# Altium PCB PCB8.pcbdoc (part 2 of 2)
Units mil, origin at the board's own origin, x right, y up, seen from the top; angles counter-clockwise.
Board outline 4659.3 x 3372.91 mil, 4 copper layers (Top Layer, Inner1, Inner2, Bottom Layer); 143 components, 120 nets, 588 pads, 154 vias.
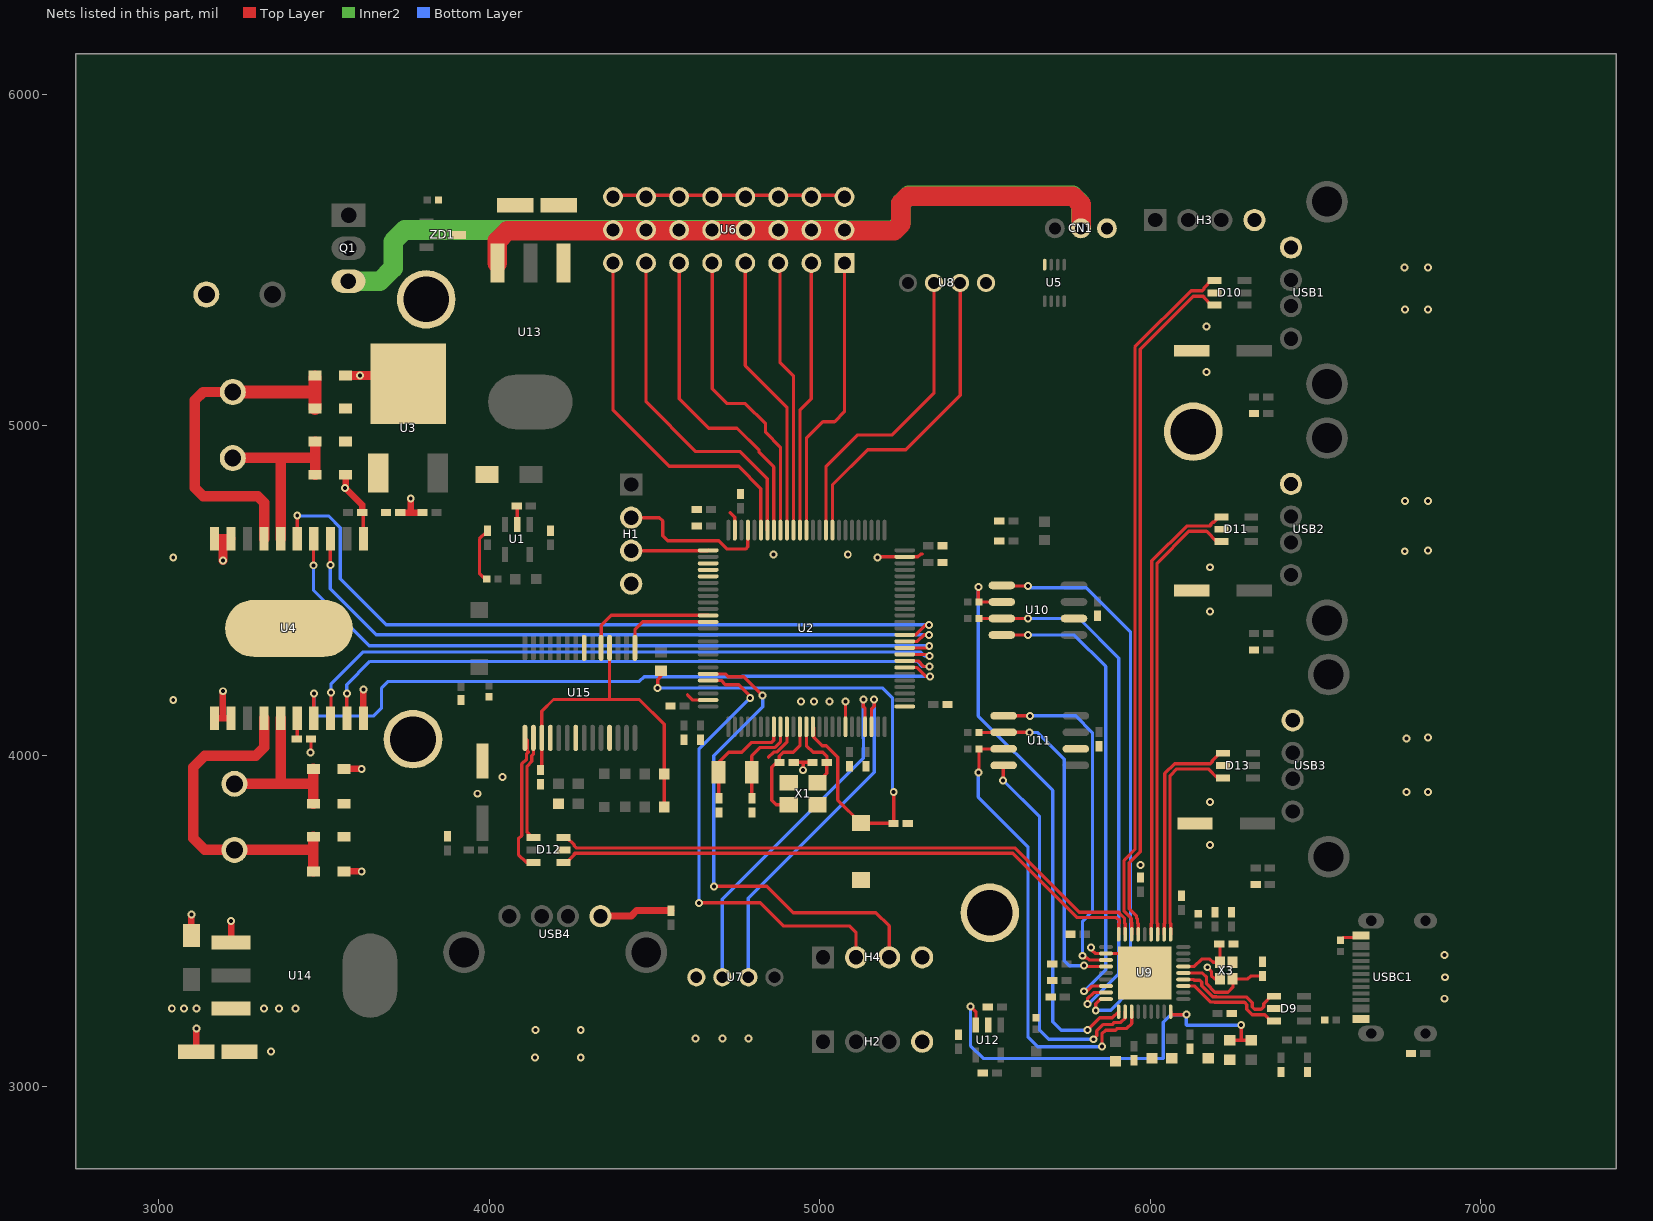
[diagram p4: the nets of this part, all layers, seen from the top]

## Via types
v1: diameter 24.02, hole 12.01, Top Layer to Bottom Layer, 154 vias

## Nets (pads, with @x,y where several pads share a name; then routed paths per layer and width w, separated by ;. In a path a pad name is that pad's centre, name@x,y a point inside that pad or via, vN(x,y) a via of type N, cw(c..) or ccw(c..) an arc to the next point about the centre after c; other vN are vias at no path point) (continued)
ENA: U2.34 U4.8 | length 2035.8
  Top Layer w10: U4.8@3520,4113.15 3522.24,4115.39 v1(3522.24,4191.06) ; U2.34@5257.24,4306.06 5327.44,4306.06 v1(5331.8,4301.7)
  Bottom Layer w10: v1(3522.24,4191.06) 3522.24,4217.04 3618.91,4313.71 5304.8,4313.71 5316.8,4301.7 v1(5331.8,4301.7)
ENB: U2.35 U4.14 | length 2165
  Top Layer w10: v1(3469.16,4575.74) 3469.16,4655.61 U4.14@3470,4656.45 ; U2.35@5257.24,4325.74 5325.43,4325.74 v1(5331.39,4331.7)
  Bottom Layer w10: v1(3469.16,4575.74) 3469.16,4500.65 3637.08,4332.73 5330.37,4332.73 v1(5331.39,4331.7)
ENC1_1: U2.22 U7.3 | length 1100.6
  Top Layer w10: v1(5132.17,4169.53) 5132.17,4147.63 5137.17,4142.63 U2.22@5137.17,4087.56
  Bottom Layer w10: U7.3@4705.63,3329.81 4705.63,3565.43 5132.17,3991.97 5132.17,4022.85 5132.4,4023.08 5132.4,4052.13 5132.17,4052.36 v1(5132.17,4169.53)
ENC1_2: U2.23 U7.2 | length 1083.3
  Top Layer w10: U2.23@5156.85,4087.56 5156.85,4141.65 5165,4149.8 v1(5165,4169.8)
  Bottom Layer w10: U7.2@4784.37,3329.81 4784.37,3569.17 5165,3949.8 v1(5165,4169.8)
ENC3_1: U2.59 U8.3 | length 975.4
  Top Layer w10: U2.59@5038.74,4682.04 5038.74,4818.54 5145,4924.8 5260,4924.8 5425,5089.8 5425,5429.17 U8.3@5424.37,5429.8
ENC3_2: U2.60 U8.2 | length 944.5
  Top Layer w10: U2.60@5019.06,4682.04 5019.06,4873.86 5115,4969.8 5220,4969.8 5345.63,5095.43 U8.2@5345.63,5429.8
GND: C1.2 C2.1 C3.1 C4.1 C5.1 C6.1 C7.1 C8.1 C9.1 C10.1 C11.1 C12.1 C13.1 C14.2 C15.2 C16.2 C17.2 C18.2 C19.1 C20.1 C21.2 C22.2 C23.1 C24.2 C25.2 C26.2 C27.1 C28.2 C29.2 C30.1 C31.1 C32.2 C33.1 C34.2 C35.1 C36.2 C37.1 C38.2 C39.2 C40.2 C41.2 C42.1 C43.1 C44.2 C45.2 C46.2 C47.2 C48.1 C50.1 C51.2 C52.2 C53.2 C54.2 C55.2 C56.2 C57.2 C58.2 C59.2 C60.1 C61.2 C62.1 CN1.3 D5.2 D6.2 D7.2 D8.2 D9.2 D10.2 D11.2 D12.2 D13.2 H1.4 H2.4 H3.4 H4.4 P3.1 pad.1 pad.2 R1.1 R3.2 R4.1 R5.2 R6.1 R7.1 R8.1 R9.1 R10.1 R15.1 R19.2 R20.1 R21.1 RST.1 U1.2 U2.10 U2.19 U2.26 U2.49 U2.74 U2.99 U3.2 U4.1 U4.2 U4.10 U4.11 U4.19 U4.20 U4.21 U5.4 U6.17 U6.18 U6.19 U6.20 U6.21 U6.22 U6.23 U6.24 U7.4 U8.4 U9.11 U9.37 U10.6 U11.6 U12.2 U13.1 U14.1 U15.7 U15.18 U15.21 U15.25 USB1.4 USB2.4 USB3.4 USB4.4 USBC1.A1 USBC1.A12 USBC1.B1 USBC1.B12 X1.2 X1.4 X3.2 X3.4 | length 3246.3
  Top Layer w10: v1(3460,4009.8) 3461.46,4011.26 C11.1@3461.46,4049.8 ; C12.1@3616.46,4734.8 3620,4731.26 U4.11@3620,4656.45 ; R1.1@3988.72,4534.01 3970.93,4551.8 3970.93,4655.3 3990.93,4675.3 4000.93,4675.3 C3.1@3995.76,4680.47 ; U1.2@4085.76,4699.43 4085.76,4752.03 C1.2@4088.54,4754.8 ; U6.24@4390,5694.8 4490,5694.8 4590,5694.8 4690,5694.8 4790,5694.8 4890,5694.8 4990,5694.8 U6.17@5090,5694.8 ; 4600,4184.8 4616.54,4168.26 U2.99@4662.76,4168.26 ; 4730,4734.8 4743.46,4721.34 U2.74@4743.46,4682.04 ; 4845,3994.8 4860.98,4010.79 4870.81,4010.79 4900.94,4040.92 U2.10@4900.94,4087.56 ; C2.1@4921.46,3979.8 4949.99,3979.8 ; v1(4950,3955.9) 4950,3979.8 ; C5.1@4978.54,3979.8 4949.99,3979.8 ; U2.19@5078.11,4087.56 v1(5078.11,4164.18) ; v1(5175,4599.8) 5176.54,4601.34 U2.49@5257.24,4601.34 5296.54,4601.34 5305,4609.8 5310,4609.8 ; v1@5825,3409.8 5833.1,3401.7 U9.11@5865.86,3401.7 5923.8,3401.7 U9.37@5982.86,3342.64 ; v1(6172.28,3360) 6185,3347.29 6185,3334.8 6195.12,3324.68 X3.4@6210.79,3324.68 ; R4.1@6575,3441.84 6583.04,3449.88 USBC1.B1@6637.59,3449.88 USBC1.A12@6637.59,3461.69 ; USBC1.A1@6637.59,3197.91 USBC1.B12@6637.59,3209.72
  Top Layer w19.68: C47.2@3100,3451.19 v1(3100,3519.8) ; C46.2@3114.62,3104.8 3115,3105.18 v1(3115,3174.8) ; U4.1@3170,4113.15 3194.15,4113.15 ; v1(3195,4194.8) 3195,4114.01 3194.15,4113.15 ; U14.1@3219.86,3434.8 3220,3434.94 v1(3220,3499.8) ; U4.2@3220,4113.15 3194.15,4113.15 ; D5.2@3561.16,3649.8 v1(3615,3649.8) ; D6.2@3561.16,3959.8 v1(3615,3959.8) ; D8.2@3566.16,4849.8 3566.16,4810.97 v1(3565,4809.8) 3616.46,4758.34 C12.1@3616.46,4734.8 ; U4.10@3620,4113.15 v1(3620,4199.8) ; C9.1@3731.46,4734.8 3763,4734.8 ; v1(3763.24,4777.64) 3763,4777.39 3763,4734.8 ; C10.1@3798.54,4734.8 3763,4734.8
  Top Layer w21.65: USB4.4@4337,3514.35 4337.45,3514.8 4430,3514.8 4446.46,3531.26 C50.1@4550,3531.26
  Top Layer w27.56: U4.20@3170,4656.45 3195.43,4656.45 ; v1(3195,4589.8) 3195,4656.03 3195.43,4656.45 ; U4.19@3220,4656.45 3195.43,4656.45 ; D7.2@3566.16,5149.8 v1(3610,5149.8) 3729.8,5149.8 U3.2@3755,5124.61
  other v1: 4139.47,3087.17 4277.4,3086.9 4625,3144.8 4705.57,3144.8 4785,3144.8 4140,3169.8 4277.4,3170.63 6890,3264.8 6890.92,3329.8 6890,3396.63 5820.01,3419.5 5970,3669.8 6180,3729.8 6180,3859.8 3965,3884.8 6775,3889.8 6840,3889.8 4041.16,3934.8 6775,4051.75 6840,4054.8 4943.69,4164.18 4983.26,4164.18 5030.28,4164.18 6180,4436.19 6180,4569.8 4860.6,4609.01 5085,4609.01 6769.56,4618.16 6840,4619.8 6770,4769.8 6840,4769.8 6170,5159.8 6170,5298.49 6770,5349.8 6839.72,5349.78 6768.78,5477 6839.72,5477
IN1: U2.32 U4.7 | length 2174.6
  Top Layer w10: U4.7@3470,4113.15 v1(3470,4188.15) ; U2.32@5257.24,4266.69 5293.11,4266.69 5320.38,4239.43 v1(5334.04,4239.43)
  Bottom Layer w10: v1(3470,4188.15) 3470,4129.86 3480,4119.86 3649.95,4119.86 3674.95,4144.86 3674.95,4204.86 3694.57,4224.48 4454.67,4224.48 4468.9,4238.7 4763.9,4238.7 4765,4239.8 5333.66,4239.8 v1(5334.04,4239.43)
IN2: U2.33 U4.9 | length 1981.5
  Top Layer w10: U4.9@3570.06,4113.15 v1(3570.06,4188.15) ; U2.33@5257.24,4286.37 5298.43,4286.37 5315.43,4269.38 v1(5332.35,4269.38)
  Bottom Layer w10: v1(3570.06,4188.15) 3570,4214.8 3640,4284.8 5295,4284.8 5310.43,4269.38 v1(5332.35,4269.38)
IN3: U2.36 U4.13 | length 2101.5
  Top Layer w10: v1(3520,4576.45) U4.13@3520,4656.45 ; U2.36@5257.24,4345.43 5295.63,4345.43 5315.68,4365.49 v1(5330.54,4365.49)
  Bottom Layer w10: v1(3520,4576.45) 3520,4504.8 3659.32,4365.49 v1(5330.54,4365.49)
IN4: U2.37 U4.15 | length 2295.2
  Top Layer w10: U4.15@3420,4656.45 v1(3420,4726.45) ; U2.37@5257.24,4365.12 5290.32,4365.12 5320.68,4395.48 v1(5330.98,4395.48)
  Bottom Layer w10: v1(3420,4726.45) 3421.65,4724.8 3515,4724.8 3550,4689.8 3550,4534.8 3689.32,4395.48 v1(5330.98,4395.48)
MISO: U2.79
MOSI: U2.80
NRST: C8.2 C49.2 RST.2 U2.14 | length 1619
  Top Layer w10: v1(4510,4204.8) 4510,4229.8 4520,4239.8 C49.2@4520,4257.24 ; U2.14@4979.69,4087.56 4982.48,4084.77 4982.48,4054.98 5007.65,4029.8 5020,4029.8 5055,3994.8 5055,3865.82 RST.2@5125,3795.82 5222.52,3795.82 C8.2@5223.54,3794.8 5223.98,3795.24 v1(5223.98,3889.61)
  Bottom Layer w10: v1(4510,4204.8) 5190,4204.8 5220,4174.8 5220,3893.59 v1(5223.98,3889.61)
OSC32_IN: C6.2 U2.8 X2.2 | length 344.9
  Top Layer w10: C6.2@4695,3871.26 4695,3948.48 X2.2@4693.79,3949.69 4693.79,3978.59 4725,4009.8 4765,4009.8 4795,4039.8 4855,4039.8 4861.57,4046.37 U2.8@4861.57,4087.56
OSC32_OUT: C7.2 U2.9 X2.1 | length 279.1
  Top Layer w10: C7.2@4795,3871.26 4795,3948.88 X2.1@4794.19,3949.69 4794.19,3998.99 4820,4024.8 4865,4024.8 4881.26,4041.06 U2.9@4881.26,4087.56
OSC_IN: C2.2 U2.12 X1.1 | length 338.5
  Top Layer w10: X1.1@4906.69,3851.34 4868.47,3851.34 4855,3864.8 4855,3964.8 4870,3979.8 C2.2@4878.54,3979.8 4877.93,3980.42 4877.93,3997.73 4890,4009.8 4920,4009.8 4940.32,4030.12 U2.12@4940.32,4087.56
OSC_OUT: C5.2 U2.13 X1.3 | length 224.5
  Top Layer w10: U2.13@4960,4087.56 4960,4029.8 4980,4009.8 5010,4009.8 5022.07,3997.73 5022.07,3980.42 C5.2@5021.46,3979.8 5021.46,3946.42 X1.3@4993.31,3918.27
OUT1: D1.2 D5.1 P1.1 U4.4 | length 1026.6
  Top Layer w31.5: U4.4@3320,4113.15 3320,4024.8 3295,3999.8 3140,3999.8 3105,3964.8 3105,3749.8 3140,3714.8 P1.1@3230,3714.8 3468.63,3714.8 3468.84,3715.01 ; D5.1@3468.84,3649.8 3468.84,3715.01 ; D1.2@3468.84,3754.8 3468.84,3715.01
OUT2: D2.2 D6.1 P1.2 U4.5 | length 542.4
  Top Layer w31.5: P1.2@3230,3914.8 3369.3,3914.8 ; U4.5@3370,4113.15 3370,3915.5 3369.3,3914.8 ; 3468.8,3914.8 3369.3,3914.8 ; D2.2@3468.84,3854.8 3468.84,3914.83 D6.1@3468.84,3959.8
OUT3: D4.2 D8.1 P2.1 U4.16 | length 594
  Top Layer w31.5: P2.1@3225,4899.8 3226.14,4900.94 3370.6,4900.94 ; U4.16@3370,4656.45 3370,4900.34 3370.6,4900.94 ; D8.1@3473.84,4849.8 3473.84,4900.94 ; D4.2@3473.84,4949.8 3473.84,4900.94 ; 3370.6,4900.94 3473.84,4900.94
OUT4: D3.2 D7.1 P2.2 U4.17 | length 1071.5
  Top Layer w31.5: P2.2@3225,5099.8 3135,5099.8 3110,5074.8 3110,4809.8 3135,4784.8 3300,4784.8 3320,4764.8 U4.17@3320,4656.45
  Top Layer w39.37: P2.2@3225,5099.8 3473.14,5099.8 3473.84,5100.5 ; D3.2@3473.84,5049.8 3473.84,5100.5 ; D7.1@3473.84,5144.8 3473.84,5100.5
PA8: U2.67 U6.5 | length 925.4
  Top Layer w10: U6.5@4675,5489.8 4675,5109.8 4720,5064.8 4775,5064.8 4836.26,5003.54 4836.26,4978.37 4881.26,4933.37 U2.67@4881.26,4682.04
PA9: U2.68 U6.6 | length 976.3
  Top Layer w10: U6.6@4575,5489.8 4575,5079.8 4665,4989.8 4750,4989.8 4816.57,4923.23 4816.57,4918.06 4861.57,4873.06 U2.68@4861.57,4682.04
PA10: U2.69 U6.7 | length 1038.8
  Top Layer w10: U6.7@4475,5489.8 4475,5069.8 4625,4919.8 4760,4919.8 4841.89,4837.91 U2.69@4841.89,4682.04
PA11: U2.70 U6.8 | length 1116
  Top Layer w10: U6.8@4375,5489.8 4375,5044.8 4545,4874.8 4755,4874.8 4822.2,4807.6 U2.70@4822.2,4682.04
PC6: U2.63 U6.1 | length 875.9
  Top Layer w10: U2.63@4960,4682.04 4960,4959.8 5010,5009.8 5045,5009.8 5075,5039.8 U6.1@5075,5489.8
PC7: U2.64 U6.2 | length 822.1
  Top Layer w10: U2.64@4940.32,4682.04 4940.32,5045.12 4975,5079.8 U6.2@4975,5489.8
PC8: U2.65 U6.3 | length 829.6
  Top Layer w10: U6.3@4875,5489.8 4880,5489.8 4880,5189.8 4920.63,5149.17 U2.65@4920.63,4682.04
PC9: U2.66 U6.4 | length 859.9
  Top Layer w10: U6.4@4775,5489.8 4775,5179.8 4900.94,5053.86 U2.66@4900.94,4682.04
RX1: U2.86 U15.5 | length 404.8
  Top Layer w10: U15.5@4338.98,4325.83 4338.98,4393.78 4370,4424.8 4662.13,4424.8 U2.86@4662.76,4424.17
SCK: U2.78
SCL: H4.3 U2.95 | length 1504.7
  Top Layer w10: U2.95@4662.76,4247 4714.93,4247 4723.24,4238.7 4770.71,4238.7 v1(4827.6,4181.81) ; v1(4680,3604.8) 4840,3604.8 4920,3524.8 5170,3524.8 5210,3484.8 H4.3@5210,3389.8
  Bottom Layer w10: v1(4680,3604.8) 4680,3999.8 4827.6,4147.4 v1(4827.6,4181.81)
SDA: H4.2 U2.96 | length 1423.4
  Top Layer w10: v1(4635,3554.8) 4820,3554.8 4890,3484.8 5090,3484.8 5110,3464.8 H4.2@5110,3389.8 ; U2.96@4662.76,4227.32 4702.48,4227.32 4715,4214.8 4755,4214.8 4790,4179.8 v1(4790,4174.8)
  Bottom Layer w10: v1(4635,3554.8) 4635,4019.8 v1(4790,4174.8)
SWCLK: H1.3 U2.76 | length 233.3
  Top Layer w10: H1.3@4430,4619.8 4661.54,4619.8 U2.76@4662.76,4621.02
SWDIO: H1.2 U2.72 | length 471.6
  Top Layer w10: H1.2@4430,4719.8 4515,4719.8 4525,4709.8 4525,4664.8 4540,4649.8 4695,4649.8 4720,4624.8 4775.76,4624.8 4782.83,4631.88 U2.72@4782.83,4682.04
TX1: U2.87 U15.1 | length 286.7
  Top Layer w10: U15.1@4441.34,4325.83 4441.34,4381.14 4465,4404.8 4662.45,4404.8 U2.87@4662.76,4404.49
USB1_DM: D12.4 U15.16 | length 319.8
  Top Layer w10: U15.16@4134.25,4053.77 4134.25,4004.1 4129.45,3999.3 4129.45,3982.68 4115,3968.22 4115,3768.46 4131.26,3752.2 D12.4@4134.76,3752.2
USB1_DP: D12.6 U15.15 | length 424.5
  Top Layer w10: U15.15@4108.66,4053.77 4116.1,4046.33 4116.1,4013.75 4118.25,4011.6 4118.25,4010.73 4113.45,4005.93 4113.45,3989.3 4099,3974.85 4099,3758.21 4089,3748.21 4089,3700.8 4112.4,3677.4 D12.6@4134.76,3677.4
USB_HUB_NOCS1: R12.1 U9.13 U11.2 | length 1034.7
  Top Layer w10: R12.1@5482.04,4069.8 5555.85,4069.8 U11.2@5556.48,4070.43 5634.37,4070.43 v1(5635,4069.8) ; v1(5800,3364.8) 5802.47,3362.33 U9.13@5865.86,3362.33
  Bottom Layer w10: v1(5635,4069.8) 5660,4069.8 5740,3989.8 5740,3379.8 5755,3364.8 v1(5800,3364.8)
USB_HUB_NOCS2: R13.2 U9.17 U10.3 | length 1639.8
  Top Layer w10: R13.2@5482.04,4414.8 U10.3@5550.85,4414.8 v1(5630,4414.8) ; v1(5810,3248.91) 5810,3264.8 5828.79,3283.59 U9.17@5865.86,3283.59
  Bottom Layer w10: v1(5630,4414.8) 5785,4414.8 5905,4294.8 5905,3339.8 5814.11,3248.91 v1(5810,3248.91)
USB_HUB_NOCS3: R11.1 U9.19 U10.2 | length 1758.1
  Top Layer w10: v1(5480,4509.8) 5480,4466.84 R11.1@5482.04,4464.8 U10.2@5550.85,4464.8 U10.2@5552.72,4462.93 ; v1(5810,3169.8) 5847.22,3207.02 5885.49,3207.02 U9.19@5904.12,3225.64
  Bottom Layer w10: v1(5480,4509.8) 5480,4119.8 5705,3894.8 5705,3194.8 5730,3169.8 v1(5810,3169.8)
USB_HUB_NOCS4: R14.2 U9.21 U11.3 | length 1421
  Top Layer w10: v1(5480,3949.17) 5482.04,3951.21 R14.2@5482.04,4019.8 5555.85,4019.8 U11.3@5556.48,4020.43 ; v1(5853.85,3120.96) 5853.85,3158.65 5865,3169.8 5895,3169.8 5900,3174.8 5928.57,3174.8 5943.49,3189.72 U9.21@5943.49,3225.64
  Bottom Layer w10: v1(5480,3949.17) 5480,3874.8 5630,3724.8 5630,3149.8 5660,3119.8 5817.48,3119.8 5818.07,3119.22 5852.11,3119.22 v1(5853.85,3120.96)
USB_HUB_PWR1: U9.12 U11.1 | length 1053.1
  Top Layer w10: U11.1@5556.48,4120.43 v1(5635.58,4120.43) ; v1(5795,3394.8) 5802.01,3387.8 5809.52,3387.8 5815.31,3382.01 U9.12@5865.86,3382.01
  Bottom Layer w10: v1(5635.58,4120.43) 5774.37,4120.43 5825,4069.8 5825,3529.8 5795,3499.8 v1(5795,3394.8)
USB_HUB_PWR2: U9.16 U10.4 | length 1435.2
  Top Layer w10: U10.4@5550.85,4364.8 v1(5630,4364.8) ; v1(5800,3287.45) 5807.64,3287.45 5823.37,3303.17 5865.76,3303.17 U9.16@5865.86,3303.27
  Bottom Layer w10: v1(5630,4364.8) 5770,4364.8 5865,4269.8 5865,3352.45 v1(5800,3287.45)
USB_HUB_PWR3: U9.18 U10.1 | length 1718.7
  Top Layer w10: U10.1@5550.85,4514.8 5552.72,4512.93 v1(5630,4512.93) ; v1(5835,3229.8) 5835,3249.8 5849.1,3263.9 U9.18@5865.86,3263.9
  Bottom Layer w10: v1(5630,4512.93) 5635,4507.93 5806.87,4507.93 5940,4374.8 5940,3289.8 5880,3229.8 v1(5835,3229.8)
USB_HUB_PWR4: U9.20 U11.4 | length 1172.1
  Top Layer w10: v1(5555,3924.8) 5555,3968.95 U11.4@5556.48,3970.43 ; v1(5827.59,3142.21) 5837.59,3152.21 5837.59,3167.39 5856.84,3186.64 5884.8,3186.64 5891.16,3193.01 5910.95,3193.01 5923.8,3205.85 U9.20@5923.8,3225.64
  Bottom Layer w10: v1(5555,3924.8) 5665,3814.8 5665,3169.8 5692.59,3142.21 v1(5827.59,3142.21)
USBDM_DN1: D13.3 U9.1 | length 660.4
  Top Layer w10: U9.1@6061.6,3459.64 6061.6,3491.3 6059.75,3493.14 6059.75,3939.55 6080,3959.8 6175,3959.8 6202.4,3932.4 D13.3@6219.76,3932.4
USBDM_DN2: D11.3 U9.3 | length 1370.7
  Top Layer w10: U9.3@6022.23,3459.64 6022.23,3491.3 6020.38,3493.14 6020.38,4582.56 6116.31,4678.49 6170,4678.49 6201.09,4647.4 D11.3@6214.76,4647.4
USBDM_DN3: D10.3 U9.6 | length 2099.3
  Top Layer w10: U9.6@5963.17,3459.64 5963.17,3491.3 5961.33,3493.14 5961.33,3505.3 5958.39,3508.24 5958.39,3514.37 5936.48,3536.28 5936.48,3676.28 5969.69,3709.49 5969.69,5229.49 6130,5389.8 6160.73,5389.8 6162.67,5387.86 6162.67,5384.78 6185.05,5362.4 D10.3@6194.76,5362.4
USBDM_DN4: D12.3 U9.8 | length 1849.8
  Top Layer w10: D12.3@4225.24,3752.2 4234.95,3752.2 4257.33,3729.83 4257.33,3726.74 4263.27,3720.8 5590.4,3720.8 5785,3526.21 5905.51,3526.21 5906.46,3525.26 5906.46,3523.85 5921.96,3508.35 5921.96,3493.14 5923.8,3491.3 U9.8@5923.8,3459.64
USBDM_UP: D9.3 U9.30 | length 326.7
  Top Layer w10: U9.30@6099.86,3303.27 6134.08,3303.27 6182.57,3254.79 6193.68,3254.79 6194.67,3253.8 6285,3253.8 6292.07,3246.73 6292.07,3233.18 6308.51,3216.73 6345.72,3216.73 6365.05,3197.4 D9.3@6374.76,3197.4
USBDP_DN1: D13.1 U9.2 | length 690.4
  Top Layer w10: U9.2@6041.91,3459.64 6041.91,3491.3 6043.75,3493.14 6043.75,3946.18 6073.37,3975.8 6181.73,3975.8 6187.67,3981.74 6187.67,3984.83 6210.05,4007.2 D13.1@6219.76,4007.2
USBDP_DN2: D11.1 U9.4 | length 1397.6
  Top Layer w10: U9.4@6002.54,3459.64 6002.54,3491.3 6004.38,3493.14 6004.38,4589.18 6109.69,4694.49 6180.42,4694.49 6182.67,4696.74 6182.67,4699.83 6189.11,4706.26 6192.19,4706.26 6208.13,4722.2 D11.1@6214.76,4722.2
USBDP_DN3: D10.1 U9.7 | length 2125.9
  Top Layer w10: U9.7@5943.49,3459.64 5943.49,3494.98 5942.39,3496.08 5942.39,3507.74 5920.48,3529.65 5920.48,3682.91 5953.69,3716.12 5953.69,5236.12 6123.37,5405.8 6156.73,5405.8 6162.67,5411.74 6162.67,5414.83 6185.05,5437.2 D10.1@6194.76,5437.2
USBDP_DN4: D12.1 U9.9 | length 1820.8
  Top Layer w10: D12.1@4225.24,3677.4 4234.95,3677.4 4257.33,3699.78 4257.33,3702.86 4259.27,3704.8 5583.78,3704.8 5778.37,3510.21 5897.47,3510.21 5905.96,3501.73 5905.96,3493.14 5904.12,3491.3 U9.9@5904.12,3459.64
USBDP_UP: D9.1 U9.31 | length 348.6
  Top Layer w10: U9.31@6099.86,3322.96 6131.51,3322.96 6133.35,3321.12 6149.98,3321.12 6155.98,3315.12 6155.98,3304 6189.19,3270.79 6200.31,3270.79 6201.3,3269.8 6291.63,3269.8 6308.07,3253.36 6308.07,3239.8 6315.14,3232.73 6335,3232.73 6342.67,3240.41 6342.67,3249.83 6365.05,3272.2 D9.1@6374.76,3272.2
VBUS_DET: R2.1 R6.2 U9.27 U12.3 | length 1333.4
  Top Layer w10: v1(5456.45,3241.75) 5472.6,3225.6 U12.3@5472.6,3185.22 ; U9.27@6061.6,3225.64 6061.6,3218.21 6063.14,3216.66 v1(6108.84,3216.66) ; R6.2@6240,3139.46 6275.27,3139.46 ; v1(6275,3184.8) 6275,3139.73 6275.27,3139.46 ; R2.1@6305,3139.46 6275.27,3139.46
  Bottom Layer w10: v1(5456.45,3241.75) 5456.45,3121.75 5494.13,3084.07 6038.76,3084.07 6038.76,3193.57 6061.86,3216.66 v1(6108.84,3216.66) 6108.84,3185.96 6110,3184.8 v1(6275,3184.8)
VCC: C9.2 C11.2 C44.1 C46.1 CN1.2 D1.1 D2.1 D3.1 D4.1 Q1.3 U3.1 U4.6 U6.9 U6.10 U6.11 U6.12 U6.13 U6.14 U6.15 U6.16 U13.3 U14.3 ZD1.3 | length 4558.4
  Top Layer w10: C11.2@3418.54,4049.8 3420,4051.26 U4.6@3420,4113.15
  Top Layer w59.06: U13.3@4025,5489.94 4025,5556.63 4055.91,5587.55 5225.91,5587.55 5245.91,5607.55 5245.91,5670.72 5267.74,5692.55 5765.91,5692.55 5790.91,5667.55 5790.91,5600.72 CN1.2@5790,5599.8
  Inner2 w59.06: Q1.3@3574.8,5434.81 3669.99,5434.8 3710,5474.8 3710,5554.8 3745,5589.8 U6.16@4375,5589.8 U6.15@4475,5589.8 U6.14@4575,5589.8 U6.13@4675,5589.8 U6.12@4775,5589.8 U6.11@4875,5589.8 U6.10@4975,5589.8 U6.9@5075,5589.8 5075.15,5589.66 5224.85,5589.66 5245.15,5609.95 5245.15,5669.66 5270.15,5694.66 5765.15,5694.66 5790,5669.8 CN1.2@5790,5594.8
  other v1: 3340,3104.8 3040.49,3234.8 3077.01,3234.8 3115,3234.8 3320,3234.8 3364.14,3234.8 3415,3234.8 3045,4167.84 3045,4599.8
VCCIO: C48.2 R17.2 R18.2 U15.4 U15.17 | length 1004.3
  Top Layer w10: C48.2@4155,3956.26 4159.84,3961.1 U15.17@4159.84,4053.77 4159.84,4134.64 4195,4169.8 4364.24,4169.8 ; U15.4@4364.57,4325.83 4364.57,4170.13 4364.24,4169.8 ; R18.2@4534.66,3844.8 4529.66,3849.8 R17.2@4529.66,3944.8 4529.66,4095.14 4455,4169.8 4364.24,4169.8
XTALIN: C40.1 U9.33 X3.3 | length 180.1
  Top Layer w10: U9.33@6099.86,3362.33 6132.53,3362.33 6155,3384.8 6180,3384.8 6189.88,3374.92 X3.3@6210.79,3374.92 6210.79,3427.55 C40.1@6208.54,3429.8
XTALOUT: C41.1 U9.32 X3.1 | length 311.6
  Top Layer w10: U9.32@6099.86,3342.64 6157.16,3342.64 6170,3329.8 6170,3309.8 6195,3284.8 6235,3284.8 6250,3299.8 6250,3323.89 X3.1@6249.21,3324.68 6294.88,3324.68 6303.54,3333.34 C41.1@6340,3333.34
pads on no net: U2.1 U2.2 U2.3 U2.4 U2.5 U2.7 U2.15 U2.16 U2.17 U2.18 U2.24 U2.25 U2.30 U2.31 U2.38 U2.39 U2.40 U2.41 U2.42 U2.43 U2.44 U2.45 U2.51 U2.55 U2.56 U2.57 U2.58 U2.61 U2.62 U2.71 U2.77 U2.81 U2.82 U2.83 U2.84 U2.85 U2.88 U2.89 U2.90 U2.91 U2.92 U2.93 U2.97 U2.98 U4.3 U4.18 U15.3 U15.6 U15.8 U15.9 U15.10 U15.11 U15.12 U15.13 U15.14 U15.24 U15.26 U15.27 U15.28 USB4.2 USB4.3 USBC1.A8 USBC1.B8 ZD1.2

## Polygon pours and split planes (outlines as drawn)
3V3_HUB on Inner2 (solid, remove dead copper): 5347.35,3003.9 5329.99,3021.27 5329.99,3127.45 5354.18,3151.64 5635.37,3152.63 5685.33,3189.8 5685.33,3548.32 5732.28,3584.8 6360,3584.8 6400,3544.8 6400,3020.78 6383.12,3003.9
VCC on Top Layer (solid, remove dead copper, pour order 0): 3000,5759.8 3757.87,5759.8 3757.87,3003.9 3000,3003.9
5V_HOST on Inner2 (solid, remove dead copper): 6447.71,3003.9 6435.91,3003.9 6430,3009.8 6430,3404.8 6470,3444.8 6720,3444.8 6760,3404.8 6760,3019.8 6744.09,3003.9
VCC on Top Layer (solid, remove dead copper, pour order 2): 3495,5474.8 3495,5389.8 3690,5389.8 3695,5394.8 3695,5419.8 3700,5424.8 3700,5444.48 3745.46,5489.94 4040.14,5489.94 4055,5504.8 4055,5549.8 4065,5559.8 4125,5559.8 4145,5579.81 4145,5705 4135,5719.8 3979.68,5719.8 3970,5705.4 3970,5634.17 3960,5614.8 3876.43,5614.8 3842.54,5574.8 3723.8,5574.8 3630,5479.8 3500,5479.8
VCC on Inner2 (solid, remove dead copper): 3000,3003.9 3747.94,3003.9 3747.94,3159.8 3660,3247.74 3660,4544.8 3750,4634.8 3750,5759.8 3000,5759.8
GND on Top Layer (solid, remove dead copper, pour order 4): 3818.11,3003.9 3818.11,5759.8 6937.01,5759.8 6937.01,3003.9
+5V on Inner2 (solid, remove dead copper): 3885,5484.8 3885,4716.73 3901.92,4699.8 4250,4699.8 4270,4719.8 4270,4969.8 4315,5014.8 5665,5014.8 5700,5049.8 5700,5124.8 5745,5169.8 5895,5169.8 5900,5174.8 5900,5444.8 5890,5454.8 5700.85,5454.8 5646.85,5508.8 5286,5508.8 5285,5509.8 5220,5444.8 5220,5354.8 5200,5334.8 4283.89,5334.8 4205,5413.7 4205,5469.8 4190,5484.8
+3V3 on Inner2 (solid, remove dead copper): 4075,4629.8 4075,4219.8 4110,4184.8 4465.16,4184.8 4590.16,4059.8 4595,4059.8 4595,4018.58 4608.59,4009.8 5175,4009.8 5230,4039.8 5315,4039.8 5355,4079.8 5355,4852.49 5328.24,4874.8 4365,4874.8 4350,4854.84 4350,4667.5 4336.59,4658.37 4105.21,4658.37 4076.64,4629.8

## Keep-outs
Board Outline Layer:
  lines w10: 3000,3084.8 ccw(c3078.74,3084.8) 3078.74,3006.06 6858.27,3006.06 ccw(c6858.27,3084.8) 6937.01,3084.8 6937.01,5681.06 ccw(c6858.27,5681.06) 6858.27,5759.8 3078.74,5759.8 ccw(c3078.74,5681.06) 3000,5681.06 3000,3084.8

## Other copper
Top Layer:
  drawing of 475 lines, arcs and shapes, not listed
Inner2:
  region net VCC: 5760.47,5630.8 5819.53,5630.8 5819.76,5606.43 5820,5594.8 5760,5594.8 5760.24,5606.43
  region net VCC: 3669.99,5464.33 3669.99,5405.27 3655.22,5405.02 3640.97,5404.35 3627.67,5403.4 3615.75,5402.32 3597.8,5400.29 3590.55,5399.37 3590.55,5470.23 3597.8,5469.31 3615.75,5467.28 3627.67,5466.2 3640.97,5465.25 3655.22,5464.58
  region net +5V: 4900.77,3349.49 4900.77,3310.12 4897.59,3310.33 4894.85,3310.84 4890.25,3311.98 4888.17,3312.22 4886.09,3311.97 4885.01,3311.61 4883.9,3311.05 4882.72,3310.28 4881.48,3309.26 4881.48,3350.35 4882.72,3349.33 4883.9,3348.55 4885.01,3348 4886.09,3347.63 4888.17,3347.39 4890.25,3347.63 4894.85,3348.76 4897.59,3349.28
  region net +5V: 4843.64,3367.62 4883.01,3367.31 4882.79,3364.12 4882.27,3361.39 4881.12,3356.8 4880.87,3354.73 4881.1,3352.65 4881.46,3351.57 4882.01,3350.45 4882.78,3349.27 4883.79,3348.02 4842.71,3348.33 4843.73,3349.56 4844.51,3350.73 4845.08,3351.84 4845.45,3352.92 4845.7,3355 4845.48,3357.09 4844.35,3361.71 4843.85,3364.45
  region net VCC: 5111.15,5619.19 5111.15,5560.13 5093,5559.93 5085.63,5559.82 5074.85,5559.8 5075.15,5619.8 5085.83,5619.67 5093.15,5619.46 5100.46,5619.27
  region net VCC: 5039,5560.28 5039,5619.33 5063.38,5619.57 5075,5619.8 5075,5559.8 5063.38,5560.04
  region net VCC: 4939,5560.28 4939,5619.33 4963.38,5619.57 4975,5619.8 4975,5559.8 4963.38,5560.04
  region net VCC: 5011,5619.33 5011,5560.28 4986.62,5560.04 4975,5559.8 4975,5619.8 4986.62,5619.57
  region net VCC: 4911,5619.33 4911,5560.28 4886.62,5560.04 4875,5559.8 4875,5619.8 4886.62,5619.57
  region net VCC: 4839,5560.28 4839,5619.33 4863.38,5619.57 4875,5619.8 4875,5559.8 4863.38,5560.04
  region net VCC: 4811,5619.33 4811,5560.28 4786.62,5560.04 4775,5559.8 4775,5619.8 4786.62,5619.57
  region net VCC: 4739,5560.28 4739,5619.33 4763.38,5619.57 4775,5619.8 4775,5559.8 4763.38,5560.04
  region net VCC: 4711,5619.33 4711,5560.28 4686.62,5560.04 4675,5559.8 4675,5619.8 4686.62,5619.57
  region net VCC: 4639,5560.28 4639,5619.33 4663.38,5619.57 4675,5619.8 4675,5559.8 4663.38,5560.04
  region net VCC: 4539,5560.28 4539,5619.33 4563.38,5619.57 4575,5619.8 4575,5559.8 4563.38,5560.04
  region net VCC: 4611,5619.33 4611,5560.28 4586.62,5560.04 4575,5559.8 4575,5619.8 4586.62,5619.57
  region net VCC: 4439,5560.28 4439,5619.33 4463.38,5619.57 4475,5619.8 4475,5559.8 4463.38,5560.04
  region net VCC: 4511,5619.33 4511,5560.28 4486.62,5560.04 4475,5559.8 4475,5619.8 4486.62,5619.57
  region net VCC: 4411,5619.33 4411,5560.28 4386.62,5560.04 4375,5559.8 4375,5619.8 4386.62,5619.57
  region net VCC: 4339,5560.28 4339,5619.33 4363.38,5619.57 4375,5619.8 4375,5559.8 4363.38,5560.04
  region net +5V_PI: 4015.67,3492.7 4015.67,3536.01 4019.2,3535.88 4022.46,3535.6 4025.48,3535.31 4028.32,3535.18 4031.05,3535.36 4033.71,3536.01 4035.04,3536.55 4036.38,3537.27 4037.72,3538.18 4039.09,3539.3 4039.09,3489.41 4037.72,3490.53 4036.38,3491.44 4035.04,3492.16 4033.71,3492.7 4031.05,3493.34 4028.32,3493.52 4025.48,3493.4 4022.46,3493.11 4019.2,3492.83
  region net +5V: 6034.69,5527.28 5995.31,5527.28 ccw(c5861.88,5527.28) 5981.54,5586.34 6048.46,5586.34 ccw(c6168.12,5527.28)
  region net +5V: 5029.69,3339.8 4990.31,3339.8 ccw(c4973.5,3339.8) 4976.54,3356.34 5043.46,3356.34 ccw(c5046.5,3339.8)
  region net +5V_USB_PORT3: 5758.19,4579.21 5781.81,4579.21 5782.01,4564.8 5757.99,4564.8
  region net +5V_USB_PORT3: 6366.81,4975.39 6343.19,4975.39 6342.99,4989.8 6367.01,4989.8
  region net 3V3_HUB: 5960.16,3563.82 5979.84,3563.82 5979.94,3561.17 5980.18,3558.67 5980.93,3554.29 5981.67,3551.07 5982.01,3549.41 5957.99,3549.41 5958.33,3551.07 5959.07,3554.29 5959.82,3558.67 5960.06,3561.17
  region net +5V_USB_PORT1: 5776.61,4183.97 5793.32,4167.27 5783.27,4156.94 5766.28,4173.92
  region net +5V_USB_PORT1: 6349.65,3584.21 6373.27,3584.21 6373.47,3569.8 6349.45,3569.8
  region net +5V_USB_PORT4: 5760.37,3913.62 5760.37,3937.24 5774.78,3937.44 5774.78,3913.42
  region net +5V_USB_PORT4: 3934.41,3771.61 3934.41,3747.99 3920,3747.8 3920,3771.81
  region net +5V_USB_PORT2: 5784.41,4326.61 5784.41,4302.99 5770,4302.8 5770,4326.81
  region net +5V_USB_PORT2: 6340.59,4267.99 6340.59,4291.61 6355,4291.81 6355,4267.8
  region net +5V_USB_FIL: 5713.54,4085.18 5699.63,4071.26 5697.69,4073.07 5695.74,4074.66 5692.12,4077.23 5689.32,4078.98 5687.91,4079.92 5704.89,4096.9 5705.82,4095.49 5707.57,4092.68 5710.14,4089.06 5711.74,4087.12
  region net +5V_USB_FIL: 5553.23,3351.95 5567.15,3338.03 5565.34,3336.1 5563.75,3334.15 5561.17,3330.53 5559.43,3327.73 5558.49,3326.31 5541.51,3343.29 5542.92,3344.23 5545.72,3345.98 5549.35,3348.55 5551.29,3350.15
  region net 3V3_HUB: 5459.41,4189.65 5459.41,4169.96 5456.76,4169.87 5454.26,4169.62 5449.88,4168.88 5446.66,4168.13 5445,4167.8 5445,4191.81 5446.66,4191.47 5449.88,4190.73 5454.26,4189.98 5456.76,4189.74
  region net +5V-D1: 3854.84,4765.39 3835.16,4765.39 3835.06,4768.04 3834.82,4770.54 3834.07,4774.93 3833.33,4778.14 3832.99,4779.8 3857.01,4779.8 3856.67,4778.14 3855.93,4774.93 3855.18,4770.54 3854.94,4768.04
  region net +5V-D1: 3549.84,4775.39 3530.16,4775.39 3530.06,4778.04 3529.82,4780.54 3529.07,4784.93 3528.33,4788.14 3527.99,4789.8 3552.01,4789.8 3551.67,4788.14 3550.93,4784.93 3550.18,4780.54 3549.94,4778.04
Bottom Layer:
  region net ENC1_2: 4779.37,3367.47 4789.37,3367.47 4789.46,3365.43 4789.72,3363.65 4790.14,3362.1 4790.71,3360.76 4791.41,3359.58 4792.24,3358.53 4794.23,3356.71 4799.2,3353.22 4802.01,3351.02 4804.91,3348.18 4763.83,3348.18 4766.73,3351.02 4769.54,3353.22 4774.51,3356.71 4776.5,3358.53 4777.33,3359.58 4778.03,3360.76 4778.6,3362.1 4779.02,3363.65 4779.28,3365.43
  region net ENC1_1: 4700.63,3367.47 4710.63,3367.47 4710.72,3365.43 4710.98,3363.65 4711.4,3362.1 4711.97,3360.76 4712.67,3359.58 4713.5,3358.53 4715.49,3356.71 4720.46,3353.22 4723.27,3351.02 4726.17,3348.18 4685.09,3348.18 4687.99,3351.02 4690.8,3353.22 4695.77,3356.71 4697.76,3358.53 4698.59,3359.58 4699.29,3360.76 4699.86,3362.1 4700.28,3363.65 4700.54,3365.43
  region net DEBUG_RX: 5095,3172.07 5105,3186.97 5105.13,3184.66 5105.5,3182.54 5106.09,3180.59 5106.9,3178.8 5107.9,3177.16 5109.09,3175.64 5110.43,3174.23 5111.92,3172.9 5115.27,3170.46 5119.01,3168.18 5127.14,3163.55 5079.53,3148.64 5080.34,3150.2 5081.31,3151.71 5083.58,3154.58 5088.72,3160.04 5091.12,3162.79 5093.13,3165.66 5093.9,3167.16 5094.49,3168.72 5094.87,3170.36
  region net DEBUG_TX: 5205,3180.54 5215,3180.54 5215.11,3177.93 5215.45,3175.7 5215.99,3173.78 5216.71,3172.14 5217.62,3170.72 5218.68,3169.49 5219.89,3168.4 5221.23,3167.4 5224.25,3165.48 5227.62,3163.37 5231.22,3160.71 5233.08,3159.05 5234.94,3157.11 5185.06,3157.11 5186.92,3159.05 5188.78,3160.71 5192.38,3163.37 5195.75,3165.48 5198.77,3167.4 5200.11,3168.4 5201.32,3169.49 5202.38,3170.72 5203.29,3172.14 5204.01,3173.78 5204.55,3175.7 5204.89,3177.93
  region net ENA: 3517.24,4207.47 3527.24,4207.47 3527.33,4206.35 3527.58,4205.22 3528.47,4202.99 3529.74,4200.9 3531.19,4199.07 3513.29,4199.07 3514.74,4200.9 3516.01,4202.99 3516.9,4205.22 3517.15,4206.35
  region net ENB: 3474.16,4559.33 3464.16,4559.33 3464.07,4560.45 3463.82,4561.59 3462.92,4563.82 3461.66,4565.91 3460.21,4567.74 3478.11,4567.74 3476.66,4565.91 3475.39,4563.82 3474.5,4561.59 3474.25,4560.45
  region net VBUS_DET: 6092.43,3211.66 6092.43,3221.66 6093.55,3221.75 6094.68,3222 6096.91,3222.89 6099.01,3224.16 6100.83,3225.61 6100.83,3207.71 6099.01,3209.16 6096.91,3210.43 6094.68,3211.32 6093.55,3211.57
  region net VBUS_DET: 6113.84,3200.25 6103.84,3200.25 6103.75,3201.37 6103.5,3202.5 6102.61,3204.73 6101.34,3206.83 6099.89,3208.65 6117.79,3208.65 6116.34,3206.83 6115.07,3204.73 6114.18,3202.5 6113.93,3201.37
  region net USB_HUB_NOCS4: 5838.81,3114.22 5836.23,3124.22 5837.34,3124.32 5838.5,3124.6 5840.82,3125.61 5842.94,3127.03 5844.63,3128.66 5847.22,3110.94 5845.28,3112.15 5843.2,3113.2 5841.03,3113.94
  region net USB_HUB_NOCS3: 5793.59,3164.8 5793.59,3174.8 5794.71,3174.89 5795.84,3175.14 5798.07,3176.04 5800.17,3177.3 5801.99,3178.75 5801.99,3160.85 5800.17,3162.3 5798.07,3163.57 5795.84,3164.46 5794.71,3164.72
  region net USB_HUB_PWR3: 5851.41,3234.8 5851.41,3224.8 5850.29,3224.72 5849.16,3224.46 5846.93,3223.57 5844.83,3222.3 5843.01,3220.85 5843.01,3238.75 5844.83,3237.3 5846.93,3236.04 5849.16,3235.14 5850.29,3234.89
  region net USB_HUB_NOCS2: 5821.49,3263.36 5825.49,3253.23 5824.12,3251.52 5823.03,3249.57 5822.17,3247.48 5821.47,3245.36 5812.25,3260.71 5813.36,3260.59 5814.58,3260.62 5817.16,3261.09 5819.59,3262.03 5820.63,3262.65
  region net USB_HUB_PWR2: 5808.07,3302.59 5815.14,3295.52 5814.41,3294.66 5813.79,3293.68 5812.84,3291.47 5812.26,3289.1 5811.99,3286.78 5799.33,3299.44 5801.65,3299.7 5804.02,3300.29 5806.24,3301.23 5807.21,3301.86
  region net USB_HUB_NOCS1: 5783.59,3359.8 5783.59,3369.8 5784.71,3369.89 5785.84,3370.14 5788.07,3371.04 5790.17,3372.3 5791.99,3373.75 5791.99,3355.85 5790.17,3357.3 5788.07,3358.57 5785.84,3359.46 5784.71,3359.72
  region net USB_HUB_PWR1: 5790,3411.21 5800,3411.21 5800.09,3410.09 5800.34,3408.96 5801.23,3406.73 5802.5,3404.64 5803.95,3402.81 5786.05,3402.81 5787.5,3404.64 5788.77,3406.73 5789.66,3408.96 5789.91,3410.09
  region net VBUS_DET: 6258.59,3179.8 6258.59,3189.8 6259.71,3189.89 6260.84,3190.14 6263.07,3191.04 6265.17,3192.3 6266.99,3193.75 6266.99,3175.85 6265.17,3177.3 6263.07,3178.57 6260.84,3179.46 6259.71,3179.72
  region net USB_HUB_PWR1: 5651.99,4125.43 5651.99,4115.43 5650.87,4115.34 5649.74,4115.09 5647.5,4114.2 5645.41,4112.93 5643.58,4111.48 5643.58,4129.38 5645.41,4127.93 5647.5,4126.66 5649.74,4125.77 5650.87,4125.52
  region net USB_HUB_NOCS1: 5651.41,4074.8 5651.41,4064.8 5650.29,4064.72 5649.16,4064.46 5646.93,4063.57 5644.83,4062.3 5643.01,4060.85 5643.01,4078.75 5644.83,4077.3 5646.93,4076.04 5649.16,4075.14 5650.29,4074.89
  region net USB_HUB_PWR4: 5570.14,3916.74 5563.07,3909.66 5562.21,3910.39 5561.24,3911.02 5559.02,3911.96 5556.65,3912.55 5554.33,3912.81 5566.99,3925.47 5567.26,3923.15 5567.84,3920.78 5568.79,3918.57 5569.41,3917.59
  region net USB_HUB_NOCS4: 5485,3932.75 5475,3932.75 5474.91,3933.88 5474.66,3935.01 5473.77,3937.24 5472.5,3939.33 5471.05,3941.16 5488.95,3941.16 5487.5,3939.33 5486.23,3937.24 5485.34,3935.01 5485.09,3933.88
  region net USB_HUB_PWR2: 5646.41,4369.8 5646.41,4359.8 5645.29,4359.72 5644.16,4359.46 5641.93,4358.57 5639.83,4357.3 5638.01,4355.85 5638.01,4373.75 5639.83,4372.3 5641.93,4371.04 5644.16,4370.14 5645.29,4369.89
  region net USB_HUB_NOCS2: 5646.41,4419.8 5646.41,4409.8 5645.29,4409.72 5644.16,4409.46 5641.93,4408.57 5639.83,4407.3 5638.01,4405.85 5638.01,4423.75 5639.83,4422.3 5641.93,4421.04 5644.16,4420.14 5645.29,4419.89
  region net USB_HUB_PWR3: 5649.41,4512.93 5643.41,4502.93 5641.13,4502.81 5638.44,4502.48 5635.76,4502.01 5633.55,4501.46 5641.01,4517.73 5641.6,4516.7 5642.41,4515.76 5643.39,4514.94 5644.5,4514.25 5645.7,4513.69 5646.94,4513.27 5648.2,4513.02
  region net USB_HUB_NOCS3: 5485,4493.39 5475,4493.39 5474.91,4494.51 5474.66,4495.65 5473.77,4497.88 5472.5,4499.97 5471.05,4501.8 5488.95,4501.8 5487.5,4499.97 5486.23,4497.88 5485.34,4495.65 5485.09,4494.51
  region net VBUS_DET: 5461.45,3225.34 5451.45,3225.34 5451.36,3226.46 5451.11,3227.59 5450.22,3229.82 5448.95,3231.91 5447.5,3233.74 5465.4,3233.74 5463.95,3231.91 5462.69,3229.82 5461.79,3227.59 5461.54,3226.46
  region net ENC1_1: 5137.17,4153.11 5127.17,4153.11 5127.08,4154.24 5126.83,4155.37 5125.94,4157.6 5124.67,4159.69 5123.22,4161.52 5141.12,4161.52 5139.67,4159.69 5138.4,4157.6 5137.51,4155.37 5137.26,4154.24
  region net ENC1_2: 5170,4153.39 5160,4153.39 5159.91,4154.51 5159.66,4155.65 5158.77,4157.88 5157.5,4159.97 5156.05,4161.8 5173.95,4161.8 5172.5,4159.97 5171.23,4157.88 5170.34,4155.65 5170.09,4154.51
  region net ENB: 5314.25,4327.73 5315.77,4337.73 5316.89,4337.81 5318.01,4338.03 5320.2,4338.85 5322.28,4339.99 5324.18,4341.3 5322.65,4323.47 5320.9,4325.03 5318.79,4326.4 5316.51,4327.36 5315.37,4327.63
  region net ENA: 5316.8,4296.7 5316.8,4306.7 5317.86,4306.79 5318.84,4307.04 5320.58,4307.94 5322.19,4309.2 5323.8,4310.65 5323.8,4292.75 5322.19,4294.2 5320.58,4295.47 5318.84,4296.36 5317.86,4296.62
  region net NRST: 5215,3902.6 5225,3908.53 5225.1,3907.4 5225.39,3906.2 5226.44,3903.77 5227.96,3901.62 5228.84,3900.77 5229.77,3900.13 5212.88,3894.19 5213.66,3896.2 5214.34,3898.32 5214.82,3900.48
  region net NRST: 4526.41,4209.8 4526.41,4199.8 4525.29,4199.72 4524.16,4199.46 4521.93,4198.57 4519.83,4197.3 4518.01,4195.85 4518.01,4213.75 4519.83,4212.3 4521.93,4211.04 4524.16,4210.14 4525.29,4209.89
  region net DEBUG_RX: 5297.93,4545.52 5297.93,4555.52 5299.05,4555.61 5300.19,4555.86 5302.42,4556.75 5304.51,4558.02 5306.34,4559.47 5306.34,4541.57 5304.51,4543.02 5302.42,4544.29 5300.19,4545.18 5299.05,4545.43
  region net DEBUG_TX: 5351.45,4529.8 5347.91,4519.8 5345.71,4519.55 5343.56,4518.87 5341.48,4517.92 5339.51,4516.82 5343.04,4534.37 5344.68,4532.69 5346.82,4531.23 5349.17,4530.2 5350.34,4529.91
  region net IN3: 3525,4560.04 3515,4560.04 3514.91,4561.16 3514.66,4562.3 3513.77,4564.53 3512.5,4566.62 3511.05,4568.45 3528.95,4568.45 3527.5,4566.62 3526.23,4564.53 3525.34,4562.3 3525.09,4561.16
  region net IN4: 3437.56,4729.8 3435.11,4719.8 3432.89,4719.52 3430.71,4718.77 3428.64,4717.71 3426.7,4716.49 3429.16,4734.22 3430.86,4732.6 3432.98,4731.18 3435.29,4730.18 3436.45,4729.9
  region net IN1: 3475,4171.74 3465,4171.74 3464.91,4172.86 3464.66,4174 3463.77,4176.23 3462.5,4178.32 3461.05,4180.15 3478.95,4180.15 3477.5,4178.32 3476.23,4176.23 3475.34,4174 3475.09,4172.86
  region net IN2: 3565.02,4204.55 3575.02,4204.58 3575.11,4203.45 3575.37,4202.32 3576.27,4200.09 3577.54,4198 3578.99,4196.18 3561.09,4196.14 3562.54,4197.97 3563.8,4200.07 3564.69,4202.3 3564.94,4203.43
  region net IN2: 5315.94,4264.38 5315.94,4274.38 5317.06,4274.47 5318.19,4274.72 5320.43,4275.61 5322.52,4276.88 5324.35,4278.33 5324.35,4260.43 5322.52,4261.88 5320.43,4263.14 5318.19,4264.04 5317.06,4264.29
  region net IN1: 5317.35,4234.8 5317.91,4244.8 5319.03,4244.89 5320.16,4245.13 5322.38,4246 5324.46,4247.22 5326.32,4248.62 5325.75,4230.73 5323.95,4232.23 5321.86,4233.53 5319.61,4234.45 5318.47,4234.71
  region net IN3: 5314.13,4360.49 5314.13,4370.49 5315.25,4370.57 5316.39,4370.83 5318.62,4371.72 5320.71,4372.99 5322.54,4374.44 5322.54,4356.54 5320.71,4357.99 5318.62,4359.25 5316.39,4360.15 5315.25,4360.4
  region net IN4: 5314.56,4390.48 5314.56,4400.48 5315.69,4400.57 5316.82,4400.82 5319.05,4401.72 5321.14,4402.98 5322.97,4404.43 5322.97,4386.53 5321.14,4387.98 5319.05,4389.25 5316.82,4390.14 5315.69,4390.39
  region net SCL: 4832.6,4165.4 4822.6,4165.4 4822.51,4166.52 4822.26,4167.65 4821.36,4169.89 4820.1,4171.98 4818.65,4173.81 4836.55,4173.81 4835.1,4171.98 4833.83,4169.89 4832.94,4167.65 4832.69,4166.52
  region net BOOT: 4023.07,4263.01 4030.14,4255.94 4029.41,4255.09 4028.79,4254.11 4027.84,4251.9 4027.26,4249.52 4026.99,4247.21 4014.33,4259.86 4016.65,4260.13 4019.02,4260.71 4021.24,4261.66 4022.21,4262.28
  region net SDA: 4781.93,4159.66 4774.86,4166.74 4775.59,4167.59 4776.21,4168.57 4777.16,4170.78 4777.74,4173.15 4778.01,4175.47 4790.67,4162.81 4788.35,4162.55 4785.98,4161.96 4783.76,4161.02 4782.79,4160.39
  region net SDA: 4630,3571.21 4640,3571.21 4640.09,3570.09 4640.34,3568.96 4641.23,3566.73 4642.5,3564.64 4643.95,3562.81 4626.05,3562.81 4627.5,3564.64 4628.77,3566.73 4629.66,3568.96 4629.91,3570.09
  region net SCL: 4675,3621.21 4685,3621.21 4685.09,3620.09 4685.34,3618.96 4686.23,3616.73 4687.5,3614.64 4688.95,3612.81 4671.05,3612.81 4672.5,3614.64 4673.77,3616.73 4674.66,3618.96 4674.91,3620.09

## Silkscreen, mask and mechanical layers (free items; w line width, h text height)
Top Silkscreen Layer:
  text "IN-" at 3205,5754.8 h118.11 r180
  text "IN+" at 3445,5754.8 h118.11 r180
  text "+5V" at 6066.67,5745.48 h59.06 r180
  text "DAC" at 6220,5744.8 h59.06 r180
  text "GND" at 6371.67,5745.48 h59.06 r180
  text "PA5" at 6160,5569.8 h59.06 r180
  text "PA4" at 6285,5569.8 h59.06 r180
  text "PA11" at 4335,5429.8 h78.74 r270
  text "PA10" at 4435,5429.8 h78.74 r270
  text "PA9" at 4535,5429.8 h78.74 r270
  text "PA8" at 4635,5429.8 h78.74 r270
  text "PC9" at 4735,5429.8 h78.74 r270
  text "PC8" at 4835,5429.8 h78.74 r270
  text "PC7" at 4935,5429.8 h78.74 r270
  text "PC6" at 5035,5429.8 h78.74 r270
  text "+5V" at 5235,5384.8 h59.06 r270
  text "PD13" at 5315,5384.8 h59.06 r270
  text "PD12" at 5390,5384.8 h59.06 r270
  text "GND" at 5470,5384.8 h59.06 r270
  text "+3V3" at 4230,4789.8 h59.06
  text "DIO" at 4280,4689.8 h59.06
  text "CLK" at 4265,4584.8 h59.06
  text "GND" at 4260,4484.8 h59.06
  text "GND" at 4655,3374.8 h59.06 r90
  text "PA0" at 4735,3374.8 h59.06 r90
  text "PA1" at 4815,3374.8 h59.06 r90
  text "+5V" at 4900,3374.8 h59.06 r90
  text "SCL" at 5245,3229.8 h59.06 r90
  text "+5V" at 5045,3219.8 h59.06 r90
  text "SDA" at 5145,3219.8 h59.06 r90
  text "GND" at 5345,3219.8 h59.06 r90
  text "RX" at 5080,3019.8 h59.06
  text "TX" at 5175,3019.8 h59.06
  text "GND" at 5260,3019.8 h59.06
  text "+5V" at 4950,3014.8 h59.06
Bottom Silkscreen Layer:
  text "IN-" at 3060,5754.8 h118.11 r180
  text "IN+" at 3270,5754.8 h118.11 r180
  text "MAX /   24V" at 3160,5614.8 h78.74 r180
  text "Designed by /      P . NDIBA" at 5625,5094.8 h118.11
